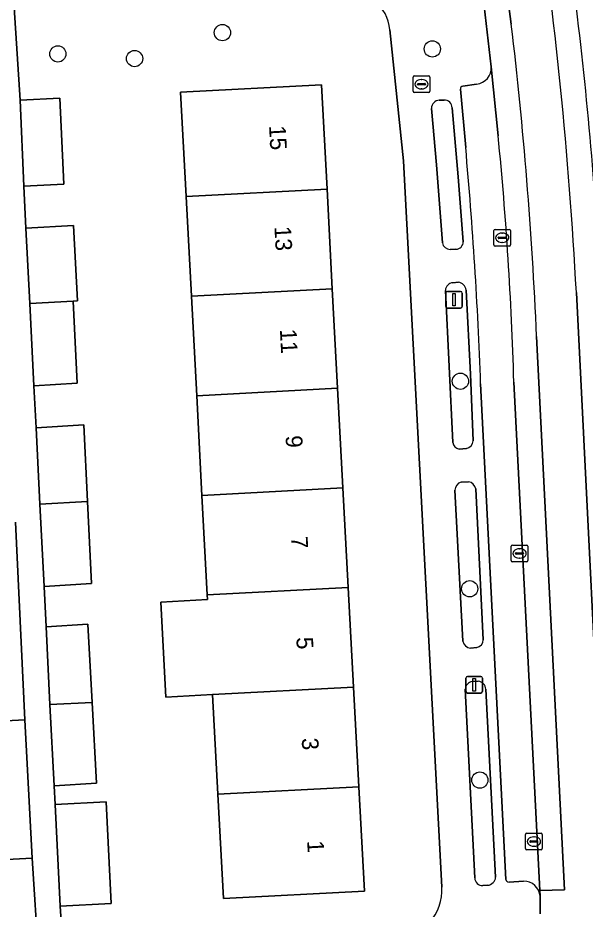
# Model space of a CAD drawing. Extents: x 160554 to 161248, y 385329 to 386506.
# Drawn here: x 161124.8 to 161158.9, y 385357 to 385410.6 of the extents above; entities that cross this region are included whole.
import ezdxf

# ---------------------------------------------------------------- set-up
doc = ezdxf.new("R2010")
doc.units = 0
for name, color, linetype in [('IMGEO_Boom', 7, 'Continuous'), ('IMGEO_Brandkraan', 7, 'Continuous'), ('IMGEO_Erf', 7, 'Continuous'), ('IMGEO_Groenvoorziening', 7, 'Continuous'), ('IMGEO_Kolk', 7, 'Continuous'), ('IMGEO_Lichtmast', 7, 'Continuous'), ('IMGEO_Pand', 7, 'Continuous'), ('IMGEO_Pand_nummerreeks', 7, 'Continuous'), ('IMGEO_Parkeervlak_open', 7, 'Continuous'), ('IMGEO_Rijbaan_lokaal_gesloten', 7, 'Continuous'), ('IMGEO_Rijbaan_lokaal_open', 7, 'Continuous'), ('IMGEO_Voetpad_open', 7, 'Continuous')]:
    doc.layers.add(name, color=color, linetype=linetype)

msp = doc.modelspace()

# ---------------------------------------------------------------- linework, layer by layer
at = {"layer": 'IMGEO_Boom'}
for centre in [(161137.101, 385409.75), (161149.732, 385408.769), (161127.199, 385408.47), (161131.816, 385408.189), (161151.422, 385388.778), (161151.979, 385376.293), (161152.589, 385364.785)]:
    msp.add_circle(centre, 0.489, dxfattribs=at)
at = {"layer": 'IMGEO_Brandkraan'}
for p, q in [((161148.578, 385406.218), (161148.578, 385407.07)), ((161148.653, 385407.144), (161149.505, 385407.144)), ((161149.579, 385407.07), (161149.579, 385406.218)), ((161148.837, 385406.638), (161148.837, 385406.65)), ((161149.275, 385406.601), (161148.877, 385406.601)), ((161148.88, 385406.687), (161149.278, 385406.687)), ((161149.066, 385406.924), (161149.091, 385406.924)), ((161149.321, 385406.65), (161149.321, 385406.638)), ((161149.505, 385406.144), (161148.653, 385406.144)), ((161149.089, 385406.364), (161149.064, 385406.364))]:
    msp.add_line(p, q, dxfattribs=at)
for points in [[(161148.578, 385406.218), (161148.578, 385407.07)], [(161148.653, 385407.144), (161149.505, 385407.144)], [(161149.579, 385407.07), (161149.579, 385406.218)], [(161149.505, 385406.144), (161148.653, 385406.144)]]:
    msp.add_lwpolyline(points, dxfattribs=at)
for centre, radius, start, end in [((161148.655, 385407.068), 0.0765, 91.552, 178.448), ((161148.655, 385407.068), 0.0765, 91.552, 178.448), ((161149.503, 385407.068), 0.0765, 1.552, 88.448), ((161149.503, 385407.068), 0.0765, 1.552, 88.448), ((161148.877, 385406.647), 0.0403, 85.8775, 175.7526), ((161148.874, 385406.637), 0.0366, 178.938, 274.7102), ((161149.278, 385406.644), 0.043, 264.8664, 352.4533), ((161149.282, 385406.649), 0.0386, 1.7309, 96.639), ((161148.655, 385406.22), 0.0765, 181.552, 268.448), ((161148.655, 385406.22), 0.0765, 181.552, 268.448), ((161149.503, 385406.22), 0.0765, 271.552, 358.448), ((161149.503, 385406.22), 0.0765, 271.552, 358.448)]:
    msp.add_arc(centre, radius, start, end, dxfattribs=at)
for centre, major_axis, ratio, start_param, end_param in [((161149.065, 385406.644), (-0.387, 0.002), 0.722429, 4.712389, 7.853982), ((161149.09, 385406.644), (-0.39, 0.002), 0.717154, 1.570796, 4.712389)]:
    msp.add_ellipse(centre, major_axis=major_axis, ratio=ratio, start_param=start_param, end_param=end_param, dxfattribs=at)
at = {"layer": 'IMGEO_Erf'}
for points in [[(161124.564, 385411.253), (161124.925, 385405.692), (161127.326, 385405.8), (161127.559, 385400.624), (161125.158, 385400.516), (161125.28, 385397.986), (161128.134, 385398.146), (161128.382, 385393.612), (161128.118, 385393.598), (161128.361, 385388.652), (161125.759, 385388.494), (161125.887, 385385.972), (161128.77, 385386.158), (161128.993, 385381.545), (161129.231, 385376.608), (161126.368, 385376.433), (161126.49, 385374.008), (161129.005, 385374.17), (161129.258, 385369.458), (161129.518, 385364.596), (161126.973, 385364.435), (161127.03, 385363.314), (161130.103, 385363.471), (161130.414, 385357.358), (161127.341, 385357.202), (161127.536, 385354.22)], [(161147.997, 385402.036), (161147.18, 385409.927)], [(161150.308, 385358.346), (161147.997, 385402.036)], [(161088.643, 385352.265), (161126.04, 385354.145), (161125.647, 385360.086), (161119.571, 385359.767), (161113.579, 385359.452), (161107.588, 385359.137), (161101.596, 385358.822), (161095.604, 385358.507), (161089.531, 385358.188), (161089.093, 385366.516), (161095.167, 385366.835), (161101.159, 385367.15), (161107.151, 385367.465), (161113.142, 385367.78), (161119.134, 385368.095), (161125.21, 385368.414), (161124.658, 385380.293)]]:
    msp.add_lwpolyline(points, dxfattribs=at)
msp.add_lwpolyline([(161136.205, 385375.644), (161136.19, 385375.919), (161135.871, 385381.911), (161135.552, 385387.902), (161135.233, 385393.894), (161134.914, 385399.885), (161134.579, 385406.164), (161143.059, 385406.615), (161143.394, 385400.336), (161143.713, 385394.345), (161144.032, 385388.353), (161144.351, 385382.362), (161144.67, 385376.37), (161144.989, 385370.378), (161145.309, 385364.387), (161145.643, 385358.111), (161137.163, 385357.66), (161136.829, 385363.936), (161136.509, 385369.927), (161133.705, 385369.778), (161133.401, 385375.495)], close=True, dxfattribs=at)
for centre, radius, start, end in [((161144.558, 385409.657), 2.636, 5.878, 92.8817), ((161147.348, 385358.184), 2.964, 272.9757, 3.127)]:
    msp.add_arc(centre, radius, start, end, dxfattribs=at)
at = {"layer": 'IMGEO_Groenvoorziening'}
for points in [[(161150.437, 385405.691), (161150.15, 385405.679)], [(161149.682, 385405.194), (161149.972, 385401.792), (161150.337, 385397.107)], [(161151.592, 385397.168), (161151.281, 385401.07), (161150.918, 385405.234)], [(161150.798, 385396.7), (161151.148, 385396.716)], [(161151.298, 385394.729), (161150.962, 385394.704)], [(161150.52, 385394.243), (161150.96, 385385.087)], [(161152.195, 385385.195), (161152.017, 385389.2), (161151.759, 385394.26)], [(161151.346, 385384.695), (161151.778, 385384.74)], [(161151.908, 385382.725), (161151.464, 385382.71)], [(161152.792, 385373.221), (161152.338, 385382.299)], [(161151.091, 385382.222), (161151.558, 385373.14)], [(161152.031, 385372.723), (161152.405, 385372.752)], [(161152.488, 385370.726), (161152.141, 385370.722)], [(161151.703, 385370.246), (161152.281, 385358.897)], [(161153.537, 385358.946), (161152.952, 385370.251)], [(161152.768, 385358.444), (161153.059, 385358.454)]]:
    msp.add_lwpolyline(points, dxfattribs=at)
for centre, radius, start, end in [((161150.16, 385405.201), 0.478, 91.1981, 180.8458), ((161150.46, 385405.234), 0.458, 0.0574, 92.8739), ((161150.811, 385397.179), 0.479, 188.6187, 268.5011), ((161151.136, 385397.172), 0.456, 271.5391, 359.484), ((161151.005, 385394.22), 0.486, 95.0853, 177.3254), ((161151.239, 385394.21), 0.522, 5.4595, 83.5548), ((161151.435, 385385.169), 0.482, 189.7581, 259.3582), ((161151.67, 385385.258), 0.529, 281.8155, 353.175), ((161151.604, 385382.216), 0.513, 105.8406, 179.3749), ((161151.841, 385382.227), 0.502, 8.2246, 82.3109), ((161152.297, 385373.235), 0.495, 282.5833, 358.3606), ((161152.09, 385373.266), 0.546, 193.3558, 263.845), ((161152.232, 385370.199), 0.531, 99.848, 174.9135), ((161152.445, 385370.22), 0.508, 3.4888, 85.1688), ((161152.743, 385358.905), 0.462, 181.0272, 273.1158), ((161153.005, 385358.985), 0.533, 275.7961, 355.8577)]:
    msp.add_arc(centre, radius, start, end, dxfattribs=at)
at = {"layer": 'IMGEO_Kolk'}
for p, q in [((161153.434, 385396.985), (161153.434, 385397.837)), ((161153.509, 385397.911), (161154.361, 385397.911)), ((161154.435, 385397.837), (161154.435, 385396.985)), ((161153.693, 385397.405), (161153.693, 385397.417)), ((161154.131, 385397.368), (161153.733, 385397.368)), ((161153.736, 385397.454), (161154.134, 385397.454)), ((161153.922, 385397.691), (161153.947, 385397.691)), ((161154.177, 385397.417), (161154.177, 385397.405)), ((161154.361, 385396.911), (161153.509, 385396.911)), ((161153.945, 385397.131), (161153.92, 385397.131)), ((161154.48, 385377.995), (161154.48, 385378.847)), ((161154.555, 385378.921), (161155.407, 385378.921)), ((161154.968, 385378.701), (161154.993, 385378.701)), ((161155.481, 385378.847), (161155.481, 385377.995)), ((161154.739, 385378.415), (161154.739, 385378.427)), ((161155.177, 385378.378), (161154.779, 385378.378)), ((161154.782, 385378.464), (161155.18, 385378.464)), ((161154.991, 385378.141), (161154.966, 385378.141)), ((161155.223, 385378.427), (161155.223, 385378.415)), ((161155.407, 385377.921), (161154.555, 385377.921)), ((161155.343, 385360.661), (161155.343, 385361.513)), ((161155.418, 385361.587), (161156.27, 385361.587)), ((161155.831, 385361.367), (161155.856, 385361.367)), ((161156.344, 385361.513), (161156.344, 385360.661)), ((161155.602, 385361.081), (161155.602, 385361.093)), ((161156.04, 385361.044), (161155.642, 385361.044)), ((161155.645, 385361.13), (161156.043, 385361.13)), ((161156.086, 385361.093), (161156.086, 385361.081)), ((161156.27, 385360.587), (161155.418, 385360.587)), ((161155.854, 385360.807), (161155.829, 385360.807))]:
    msp.add_line(p, q, dxfattribs=at)
for points in [[(161153.434, 385396.985), (161153.434, 385397.837)], [(161153.509, 385397.911), (161154.361, 385397.911)], [(161154.435, 385397.837), (161154.435, 385396.985)], [(161154.361, 385396.911), (161153.509, 385396.911)], [(161154.48, 385377.995), (161154.48, 385378.847)], [(161154.555, 385378.921), (161155.407, 385378.921)], [(161155.481, 385378.847), (161155.481, 385377.995)], [(161155.407, 385377.921), (161154.555, 385377.921)], [(161155.343, 385360.661), (161155.343, 385361.513)], [(161155.418, 385361.587), (161156.27, 385361.587)], [(161156.344, 385361.513), (161156.344, 385360.661)], [(161156.27, 385360.587), (161155.418, 385360.587)]]:
    msp.add_lwpolyline(points, dxfattribs=at)
for centre, radius, start, end in [((161153.511, 385397.835), 0.0765, 91.552, 178.448), ((161153.511, 385397.835), 0.0765, 91.552, 178.448), ((161154.359, 385397.835), 0.0765, 1.552, 88.448), ((161154.359, 385397.835), 0.0765, 1.552, 88.448), ((161153.733, 385397.414), 0.0403, 85.8775, 175.7526), ((161153.73, 385397.404), 0.0366, 178.938, 274.7102), ((161154.134, 385397.411), 0.043, 264.8664, 352.4533), ((161154.138, 385397.416), 0.0386, 1.7309, 96.639), ((161153.511, 385396.987), 0.0765, 181.552, 268.448), ((161153.511, 385396.987), 0.0765, 181.552, 268.448), ((161154.359, 385396.987), 0.0765, 271.552, 358.448), ((161154.359, 385396.987), 0.0765, 271.552, 358.448), ((161154.557, 385378.845), 0.0765, 91.552, 178.448), ((161154.557, 385378.845), 0.0765, 91.552, 178.448), ((161155.405, 385378.845), 0.0765, 1.552, 88.448), ((161155.405, 385378.845), 0.0765, 1.552, 88.448), ((161154.557, 385377.997), 0.0765, 181.552, 268.448), ((161154.557, 385377.997), 0.0765, 181.552, 268.448), ((161154.779, 385378.424), 0.0403, 85.8775, 175.7526), ((161154.776, 385378.414), 0.0366, 178.938, 274.7102), ((161155.18, 385378.421), 0.043, 264.8664, 352.4533), ((161155.184, 385378.426), 0.0386, 1.7309, 96.639), ((161155.405, 385377.997), 0.0765, 271.552, 358.448), ((161155.405, 385377.997), 0.0765, 271.552, 358.448), ((161155.42, 385361.511), 0.0765, 91.552, 178.448), ((161155.42, 385361.511), 0.0765, 91.552, 178.448), ((161156.268, 385361.511), 0.0765, 1.552, 88.448), ((161156.268, 385361.511), 0.0765, 1.552, 88.448), ((161155.642, 385361.09), 0.0403, 85.8775, 175.7526), ((161155.639, 385361.08), 0.0366, 178.938, 274.7102), ((161156.043, 385361.087), 0.043, 264.8664, 352.4533), ((161156.047, 385361.092), 0.0386, 1.7309, 96.639), ((161155.42, 385360.663), 0.0765, 181.552, 268.448), ((161155.42, 385360.663), 0.0765, 181.552, 268.448), ((161156.268, 385360.663), 0.0765, 271.552, 358.448), ((161156.268, 385360.663), 0.0765, 271.552, 358.448)]:
    msp.add_arc(centre, radius, start, end, dxfattribs=at)
for centre, major_axis, ratio, start_param, end_param in [((161153.921, 385397.411), (-0.387, 0.002), 0.722429, 4.712389, 7.853982), ((161153.946, 385397.411), (-0.39, 0.002), 0.717154, 1.570796, 4.712389), ((161154.967, 385378.421), (-0.387, 0.002), 0.722429, 4.712389, 7.853982), ((161154.992, 385378.421), (-0.39, 0.002), 0.717154, 1.570796, 4.712389), ((161155.83, 385361.087), (-0.387, 0.002), 0.722429, 4.712389, 7.853982), ((161155.855, 385361.087), (-0.39, 0.002), 0.717154, 1.570796, 4.712389)]:
    msp.add_ellipse(centre, major_axis=major_axis, ratio=ratio, start_param=start_param, end_param=end_param, dxfattribs=at)
at = {"layer": 'IMGEO_Lichtmast'}
for p, q in [((161150.539, 385393.283), (161150.539, 385394.083)), ((161150.539, 385394.083), (161150.539, 385393.283)), ((161150.639, 385394.183), (161151.429, 385394.183)), ((161151.429, 385394.183), (161150.639, 385394.183)), ((161151.529, 385394.083), (161151.529, 385393.283)), ((161151.529, 385393.283), (161151.529, 385394.083)), ((161151.429, 385393.183), (161150.639, 385393.183)), ((161150.639, 385393.183), (161151.429, 385393.183)), ((161151.854, 385371.018), (161152.644, 385371.018)), ((161152.644, 385371.018), (161151.854, 385371.018)), ((161151.754, 385370.118), (161151.754, 385370.918)), ((161151.754, 385370.918), (161151.754, 385370.118)), ((161152.744, 385370.918), (161152.744, 385370.118)), ((161152.744, 385370.118), (161152.744, 385370.918)), ((161152.644, 385370.018), (161151.854, 385370.018)), ((161151.854, 385370.018), (161152.644, 385370.018))]:
    msp.add_line(p, q, dxfattribs=at)
for points in [[(161150.959, 385394.058), (161151.109, 385394.058), (161151.109, 385393.308), (161150.959, 385393.308), (161150.959, 385394.058)], [(161152.174, 385370.893), (161152.324, 385370.893), (161152.324, 385370.143), (161152.174, 385370.143), (161152.174, 385370.893)]]:
    msp.add_lwpolyline(points, dxfattribs=at)
for centre, start, end in [((161150.639, 385394.083), 90, 180), ((161150.639, 385394.083), 90, 180), ((161151.429, 385394.083), 0, 90), ((161151.429, 385394.083), 360, 90), ((161150.639, 385393.283), 180, 270), ((161150.639, 385393.283), 180, 270), ((161151.429, 385393.283), 270, 0), ((161151.429, 385393.283), 270, 0), ((161151.854, 385370.918), 90, 180), ((161151.854, 385370.918), 90, 180), ((161152.644, 385370.918), 0, 90), ((161152.644, 385370.918), 360, 90), ((161151.854, 385370.118), 180, 270), ((161151.854, 385370.118), 180, 270), ((161152.644, 385370.118), 270, 0), ((161152.644, 385370.118), 270, 0)]:
    msp.add_arc(centre, 0.1, start, end, dxfattribs=at)
at = {"layer": 'IMGEO_Pand'}
for points in [[(161143.394, 385400.336), (161143.059, 385406.615), (161134.579, 385406.164), (161134.914, 385399.885)], [(161124.925, 385405.692), (161125.158, 385400.516), (161127.559, 385400.624), (161127.326, 385405.8)], [(161143.713, 385394.345), (161143.394, 385400.336), (161134.914, 385399.885), (161135.233, 385393.894)], [(161128.134, 385398.146), (161125.28, 385397.986), (161125.509, 385393.459), (161128.118, 385393.598), (161128.382, 385393.612)], [(161135.233, 385393.894), (161135.552, 385387.902), (161144.032, 385388.353), (161143.713, 385394.345)], [(161128.118, 385393.598), (161125.509, 385393.459), (161125.759, 385388.494), (161128.361, 385388.652)], [(161135.552, 385387.902), (161135.871, 385381.911), (161144.351, 385382.362), (161144.032, 385388.353)], [(161128.993, 385381.545), (161128.77, 385386.158), (161125.887, 385385.972), (161126.118, 385381.391)], [(161144.67, 385376.37), (161144.351, 385382.362), (161135.871, 385381.911), (161136.19, 385375.919)], [(161126.118, 385381.391), (161126.368, 385376.433), (161129.231, 385376.608), (161128.993, 385381.545)], [(161144.67, 385376.37), (161136.19, 385375.919), (161136.205, 385375.644), (161133.401, 385375.495), (161133.705, 385369.778), (161136.509, 385369.927), (161144.989, 385370.378)], [(161126.49, 385374.008), (161126.726, 385369.323), (161129.258, 385369.458), (161129.005, 385374.17)], [(161136.509, 385369.927), (161136.829, 385363.936), (161145.309, 385364.387), (161144.989, 385370.378)], [(161129.258, 385369.458), (161126.726, 385369.323), (161126.973, 385364.435), (161129.518, 385364.596)], [(161119.571, 385359.767), (161125.647, 385360.086), (161125.21, 385368.414), (161119.134, 385368.095)], [(161136.829, 385363.936), (161137.163, 385357.66), (161145.643, 385358.111), (161145.309, 385364.387)], [(161130.103, 385363.471), (161127.03, 385363.314), (161127.341, 385357.202), (161130.414, 385357.358)]]:
    msp.add_lwpolyline(points, close=True, dxfattribs=at)
at = {"layer": 'IMGEO_Parkeervlak_open'}
for points in [[(161153.691, 385403.544), (161153.279, 385407.691)], [(161152.391, 385406.65), (161151.559, 385406.536)], [(161151.419, 385406.344), (161151.737, 385402.833)], [(161156.217, 385357.797), (161156.199, 385358.15), (161154.637, 385388.729)], [(161152.637, 385388.62), (161154.145, 385358.81)], [(161154.352, 385358.651), (161155.217, 385358.7)]]:
    msp.add_lwpolyline(points, dxfattribs=at)
for centre, radius, start, end in [((160909.325, 385381.056), 250.9, 2.94949, 7.03961), ((161152.286, 385407.639), 0.995, 276.0749, 2.9951), ((161151.611, 385406.351), 0.193, 105.8155, 181.9879), ((160939.319, 385382.418), 215.41, 1.67893, 5.6283), ((160889.964, 385379.122), 262.845, 2.07087, 5.17566), ((161154.352, 385358.865), 0.214, 194.9754, 269.9677), ((161155.233, 385357.712), 0.988, 4.9163, 90.9196)]:
    msp.add_arc(centre, radius, start, end, dxfattribs=at)
at = {"layer": 'IMGEO_Rijbaan_lokaal_gesloten'}
for points in [[(161148.041, 385459.357), (161146.58, 385470.323), (161145.077, 385470.113), (161146.64, 385458.491), (161146.649, 385458.427), (161147.451, 385452.38), (161152.332, 385415.422), (161152.671, 385412.934), (161153.279, 385407.691), (161153.691, 385403.544)], [(161154.482, 385410.25), (161148.041, 385459.357)], [(161158.397, 385394.124), (161160.185, 385358.351), (161161.693, 385358.418), (161161.635, 385359.326), (161161.407, 385363.545), (161159.921, 385393.326), (161159.893, 385393.966)], [(161154.637, 385388.729), (161156.199, 385358.15), (161157.675, 385358.191), (161156.002, 385391.468)]]:
    msp.add_lwpolyline(points, dxfattribs=at)
for centre, radius, start, end in [((160887.545, 385379.385), 271.253, 3.11475, 8.34605), ((160909.325, 385381.056), 250.9, 2.94949, 7.03961), ((160906.604, 385380.737), 249.629, 2.46376, 6.7898), ((160939.319, 385382.418), 215.41, 1.67893, 5.6283)]:
    msp.add_arc(centre, radius, start, end, dxfattribs=at)
at = {"layer": 'IMGEO_Rijbaan_lokaal_open'}
for points in [[(161149.104, 385470.631), (161146.58, 385470.323), (161148.041, 385459.357), (161154.482, 385410.25)], [(161161.7, 385358.31), (161161.693, 385358.418), (161160.185, 385358.351), (161158.397, 385394.124)], [(161156.002, 385391.468), (161157.675, 385358.191), (161156.199, 385358.15), (161156.217, 385357.797), (161156.225, 385356.742)]]:
    msp.add_lwpolyline(points, dxfattribs=at)
for centre, radius, start, end in [((160887.545, 385379.385), 271.253, 3.11475, 8.34605), ((160906.604, 385380.737), 249.629, 2.46376, 6.7898)]:
    msp.add_arc(centre, radius, start, end, dxfattribs=at)
at = {"layer": 'IMGEO_Voetpad_open'}
for points in [[(161153.279, 385407.691), (161152.671, 385412.934), (161152.332, 385415.422)], [(161124.658, 385380.293), (161125.21, 385368.414), (161125.647, 385360.086), (161126.04, 385354.145), (161127.536, 385354.22), (161127.341, 385357.202), (161127.03, 385363.314), (161126.973, 385364.435), (161126.726, 385369.323), (161126.49, 385374.008), (161126.368, 385376.433), (161126.118, 385381.391), (161125.887, 385385.972), (161125.759, 385388.494), (161125.509, 385393.459), (161125.28, 385397.986), (161125.158, 385400.516), (161124.925, 385405.692), (161124.564, 385411.253)], [(161147.18, 385409.927), (161147.997, 385402.036), (161150.308, 385358.346)], [(161151.559, 385406.536), (161152.391, 385406.65)], [(161151.737, 385402.833), (161151.419, 385406.344)], [(161150.15, 385405.679), (161150.437, 385405.691)], [(161149.972, 385401.792), (161149.682, 385405.194)], [(161150.918, 385405.234), (161151.281, 385401.07), (161151.592, 385397.168)], [(161150.337, 385397.107), (161149.972, 385401.792)], [(161151.148, 385396.716), (161150.798, 385396.7)], [(161150.962, 385394.704), (161151.298, 385394.729)], [(161150.96, 385385.087), (161150.52, 385394.243)], [(161151.759, 385394.26), (161152.017, 385389.2), (161152.195, 385385.195)], [(161154.145, 385358.81), (161152.637, 385388.62)], [(161151.778, 385384.74), (161151.346, 385384.695)], [(161151.464, 385382.71), (161151.908, 385382.725)], [(161152.338, 385382.299), (161152.792, 385373.221)], [(161151.558, 385373.14), (161151.091, 385382.222)], [(161152.405, 385372.752), (161152.031, 385372.723)], [(161152.141, 385370.722), (161152.488, 385370.726)], [(161152.281, 385358.897), (161151.703, 385370.246)], [(161152.952, 385370.251), (161153.537, 385358.946)], [(161155.217, 385358.7), (161154.352, 385358.651)], [(161153.059, 385358.454), (161152.768, 385358.444)], [(161156.225, 385356.742), (161156.217, 385357.797)]]:
    msp.add_lwpolyline(points, dxfattribs=at)
for centre, radius, start, end in [((161144.558, 385409.657), 2.636, 5.878, 92.8817), ((161152.286, 385407.639), 0.995, 276.0749, 2.9951), ((161151.611, 385406.351), 0.193, 105.8155, 181.9879), ((161150.16, 385405.201), 0.478, 91.1981, 180.8458), ((161150.46, 385405.234), 0.458, 0.0574, 92.8739), ((160889.964, 385379.122), 262.845, 2.07087, 5.17566), ((161150.811, 385397.179), 0.479, 188.6187, 268.5011), ((161151.136, 385397.172), 0.456, 271.5391, 359.484), ((161151.005, 385394.22), 0.486, 95.0853, 177.3254), ((161151.239, 385394.21), 0.522, 5.4595, 83.5548), ((161151.435, 385385.169), 0.482, 189.7581, 259.3582), ((161151.67, 385385.258), 0.529, 281.8155, 353.175), ((161151.604, 385382.216), 0.513, 105.8406, 179.3749), ((161151.841, 385382.227), 0.502, 8.2246, 82.3109), ((161152.297, 385373.235), 0.495, 282.5833, 358.3606), ((161152.09, 385373.266), 0.546, 193.3558, 263.845), ((161152.232, 385370.199), 0.531, 99.848, 174.9135), ((161152.445, 385370.22), 0.508, 3.4888, 85.1688), ((161152.743, 385358.905), 0.462, 181.0272, 273.1158), ((161153.005, 385358.985), 0.533, 275.7961, 355.8577), ((161154.352, 385358.865), 0.214, 194.9754, 269.9677), ((161155.233, 385357.712), 0.988, 4.9163, 90.9196), ((161147.348, 385358.184), 2.964, 272.9757, 3.127)]:
    msp.add_arc(centre, radius, start, end, dxfattribs=at)

# ---------------------------------------------------------------- texts
at = {"layer": 'IMGEO_Pand_nummerreeks'}
for s, rotation, p in [('15', 273.0495, (161139.906, 385404.143)), ('13', 273.0495, (161140.229, 385398.08)), ('11', 273.0495, (161140.558, 385391.903)), ('9', 273.0495, (161140.9, 385385.494)), ('7', 273.0495, (161141.223, 385379.431)), ('5', 273.0479, (161141.546, 385373.368)), ('3', 273.0495, (161141.869, 385367.305)), ('1', 273.0495, (161142.198, 385361.129))]:
    msp.add_text(s, height=1, rotation=rotation, dxfattribs=at).set_placement(p)

doc.saveas('drawing.dxf')
